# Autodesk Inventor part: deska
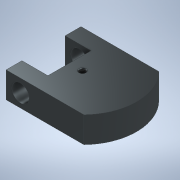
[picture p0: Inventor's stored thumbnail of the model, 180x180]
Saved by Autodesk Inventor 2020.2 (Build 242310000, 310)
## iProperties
Created: 2020-04
Part Number: deska
Material: Iron, Cast
Document SubType Name: Modeling
Designer: freem
Density: 7.15 g/cm^3
Appearance: Iron Gray
Author: freem
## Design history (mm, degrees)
sketch "Sketch1"
  geometry: L1 (9, 0)-(9, 15); L2 (9, 15)-(27, 15); L3 (27, 15)-(27, 26); L4 (27, 26)-(-27.023, 26); L5 (50.927, 0)-(-28.838, 0); L6 (9, -15)-(27, -15); L7 (27, -15)-(27, -26); L8 (27, -26)-(-27.023, -26); L9 (9, 0)-(9, -15); A1 r 37.5 centre (0, 0) between (-27.023, 26) and (-37.5, 0); A2 r 37.5 centre (0, 0) between (-37.5, 0) and (-27.023, -26); 1 further point
  constraints: 18 end point, 5 symmetric about line, 4 point on circle, 3 perpendicular, 3 point on line, 2 centre point, 1 coincident, 1 horizontal, 1 vertical, 1 other
  dimensions: "d0" = 37.5 radius of A1; "d1" = 30 distance between parallel lines of L6 L2; "d2" = 11 distance between parallel lines of L2 L4; "d3" = 27 distance from line of L7 point (0, 0); "d4" = 18 distance between parallel lines of L7 L9
extrude "Extrusion1" new body sketch "Sketch1" distance "d5" = 18; taper "d6" = 0 deg
sketch "Sketch2"
  geometry: L1 (0, 18)-(54.023, 18) reference; L2 (54.023, 0)-(54.023, 18) reference; 2 further points
  dimensions: "d7" = 9 distance from line of L1 point (44.023, 9); "d8" = 10 distance from line of L2 point (44.023, 9)
hole "Hole1" sketch "Sketch2" at (44.023, 9) diameter "d9" = 12; stored, may be unused: countersink angle "d13" = 90 deg, drill point angle "d15" = 118 deg; dims "d10" = 6, "d11" = 4, "d12" = 2, "d14" = 8
sketch "Sketch3"
  geometry: A1 r 37.5 centre (0, 0) between (27.023, -26) and (27.023, 26) reference; 2 further points
  constraints: 1 coincident
hole "Hole2" sketch "Sketch3" at (0, 0) diameter "d16" = 4.134; stored, may be unused: countersink angle "d20" = 80 deg, drill point angle "d22" = 120 deg; dims "d17" = 10, "d18" = 5, "d19" = 2, "d21" = 12
body "Solid1"
